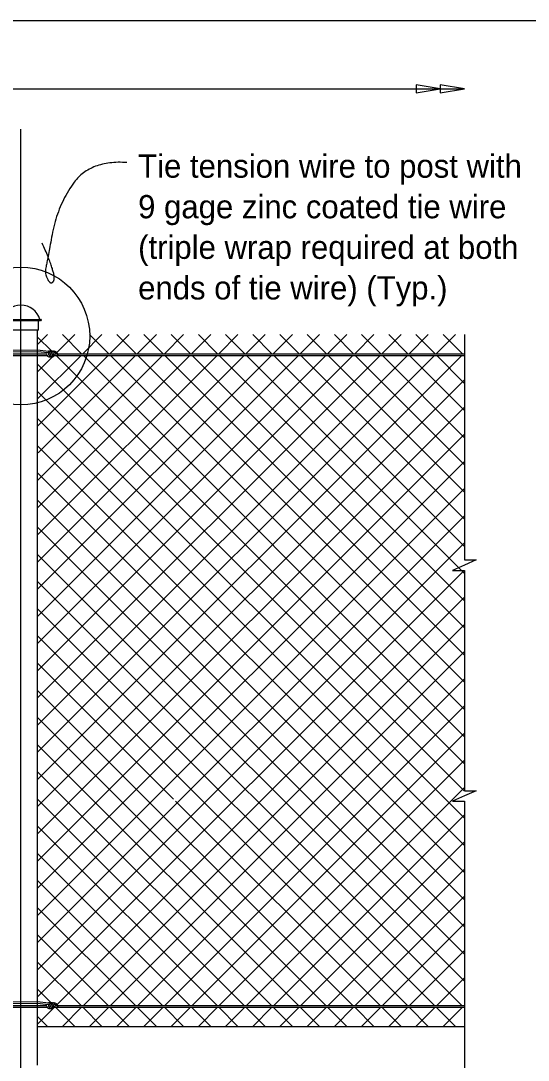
# Model space of a CAD drawing. Extents: x 0 to 72.1, y -15.2 to 30.1.
# Drawn here: x 24.63 to 29.03, y 18.99 to 28 of the extents above; entities that cross this region are included whole.
import ezdxf

# ---------------------------------------------------------------- set-up
doc = ezdxf.new("R2010")
doc.units = 0
for name, color, linetype in [('ActivePts-ConstElements', 7, 'Continuous'), ('AdhocPoint_dp', 7, 'Continuous'), ('Border', 7, 'Continuous'), ('Patterning', 7, 'Continuous'), ('PlotBorder_dp', 7, 'Continuous'), ('SheetBorder_dp', 7, 'Continuous'), ('TextMisc', 7, 'Continuous')]:
    doc.layers.add(name, color=color, linetype=linetype)

msp = doc.modelspace()

# ---------------------------------------------------------------- linework, layer by layer
at = {"layer": 'ActivePts-ConstElements'}
msp.add_lwpolyline([(0.016, 2.0538), (41.0666, 2.0538), (41.0666, 27.9999), (0.016, 27.9999)], close=True, dxfattribs=at)
at = {"layer": 'AdhocPoint_dp'}
for q in [(28.4755, 19.2783), (26.018, 19.2783)]:
    msp.add_line((24.7769, 19.2783), q, dxfattribs=at)
at = {"layer": 'Border'}
for p, q in [((24.4852, 25.1116), (24.7769, 25.1116)), ((24.4852, 25.0969), (24.7769, 25.0969)), ((24.4852, 19.4597), (24.7769, 19.4597)), ((24.4852, 19.445), (24.7769, 19.445))]:
    msp.add_line(p, q, dxfattribs=at)
at = {"layer": 'Patterning'}
for p, q in [((24.7769, 25.1917), (24.8635, 25.2783)), ((24.7769, 25.2575), (24.8992, 25.1352)), ((24.9441, 25.1232), (25.0992, 25.2783)), ((24.9918, 25.2783), (25.1584, 25.1116)), ((25.1682, 25.1116), (25.3349, 25.2783)), ((25.2275, 25.2783), (25.3941, 25.1116)), ((25.4039, 25.1116), (25.5706, 25.2783)), ((25.4632, 25.2783), (25.6298, 25.1116)), ((25.6396, 25.1116), (25.8063, 25.2783)), ((25.6989, 25.2783), (25.8655, 25.1116)), ((25.8753, 25.1116), (26.042, 25.2783)), ((25.9346, 25.2783), (26.1012, 25.1116)), ((26.111, 25.1116), (26.2777, 25.2783)), ((26.1703, 25.2783), (26.3369, 25.1116)), ((26.3467, 25.1116), (26.5134, 25.2783)), ((26.406, 25.2783), (26.5726, 25.1116)), ((26.5824, 25.1116), (26.7491, 25.2783)), ((26.6417, 25.2783), (26.8083, 25.1116)), ((26.8181, 25.1116), (26.9848, 25.2783)), ((26.8774, 25.2783), (27.044, 25.1116)), ((27.0538, 25.1116), (27.2205, 25.2783)), ((27.1131, 25.2783), (27.2797, 25.1116)), ((27.2896, 25.1116), (27.4562, 25.2783)), ((27.3488, 25.2783), (27.5154, 25.1116)), ((27.5253, 25.1116), (27.6919, 25.2783)), ((27.5845, 25.2783), (27.7511, 25.1116)), ((27.761, 25.1116), (27.9276, 25.2783)), ((27.8202, 25.2783), (27.9868, 25.1116)), ((27.9967, 25.1116), (28.1633, 25.2783)), ((28.0559, 25.2783), (28.2225, 25.1116)), ((28.2324, 25.1116), (28.399, 25.2783)), ((28.2916, 25.2783), (28.4582, 25.1116)), ((24.7769, 22.1276), (27.7462, 25.0969)), ((24.7769, 22.599), (27.2748, 25.0969)), ((24.7769, 23.0704), (26.8034, 25.0969)), ((24.7769, 23.5418), (26.332, 25.0969)), ((24.7769, 21.6562), (28.2176, 25.0969)), ((24.7769, 23.7775), (26.0963, 25.0969)), ((24.7769, 23.3061), (26.5677, 25.0969)), ((24.7769, 22.8347), (27.0391, 25.0969)), ((24.7769, 22.3633), (27.5105, 25.0969)), ((24.7769, 21.8919), (27.9819, 25.0969)), ((24.7769, 21.4205), (28.4533, 25.0969)), ((24.7769, 24.0132), (25.8606, 25.0969)), ((24.7769, 24.4846), (25.3892, 25.0969)), ((24.7769, 24.7203), (25.1535, 25.0969)), ((24.7769, 24.956), (24.9064, 25.0855)), ((24.7813, 24.2534), (25.6249, 25.0969)), ((24.9325, 25.1116), (24.937, 25.1161)), ((24.9375, 25.0969), (28.4755, 21.5588)), ((25.1732, 25.0969), (28.4755, 21.7945)), ((25.4089, 25.0969), (28.4755, 22.0302)), ((25.6446, 25.0969), (28.4755, 22.2659)), ((25.8803, 25.0969), (28.4755, 22.5016)), ((26.116, 25.0969), (28.4755, 22.7373)), ((26.3517, 25.0969), (28.4755, 22.973)), ((26.5874, 25.0969), (28.4755, 23.2087)), ((26.8231, 25.0969), (28.4755, 23.4444)), ((27.0588, 25.0969), (28.4755, 23.6801)), ((27.2945, 25.0969), (28.4755, 23.9158)), ((27.5302, 25.0969), (28.4755, 24.1515)), ((27.7659, 25.0969), (28.4755, 24.3872)), ((28.0016, 25.0969), (28.4755, 24.6229)), ((28.2373, 25.0969), (28.4755, 24.8586)), ((24.7769, 25.0218), (28.4755, 21.3231)), ((24.7769, 21.1848), (28.4755, 24.8834)), ((24.7769, 24.7861), (28.4755, 21.0874)), ((24.7769, 20.9491), (28.4755, 24.6477)), ((24.7769, 24.5503), (28.4755, 20.8517)), ((24.7769, 20.7134), (28.4755, 24.412)), ((24.7769, 24.3146), (28.4755, 20.616)), ((24.7769, 20.4777), (28.4755, 24.1763)), ((24.7769, 24.0789), (28.4755, 20.3803)), ((24.7769, 20.242), (28.4755, 23.9406)), ((24.7769, 23.8432), (28.4755, 20.1446)), ((24.7769, 20.0063), (28.4755, 23.7049)), ((24.7769, 23.6075), (28.4755, 19.9089)), ((24.7769, 19.7706), (28.4755, 23.4692)), ((24.7769, 23.3718), (28.4755, 19.6732)), ((24.7769, 19.5349), (28.4755, 23.2335)), ((24.7769, 23.1361), (28.4533, 19.4597)), ((24.9463, 19.4686), (28.4755, 22.9978)), ((24.7769, 22.9004), (28.2176, 19.4597)), ((25.1732, 19.4597), (28.4755, 22.7621)), ((24.7769, 22.6647), (27.9819, 19.4597)), ((25.4089, 19.4597), (28.4755, 22.5264)), ((24.7769, 22.429), (25.9555, 21.2505)), ((25.6446, 19.4597), (28.4755, 22.2907)), ((24.7769, 22.1933), (27.5105, 19.4597)), ((25.8803, 19.4597), (28.4755, 22.055)), ((24.7769, 21.9576), (27.2748, 19.4597)), ((26.116, 19.4597), (28.4755, 21.8193)), ((24.7769, 21.7219), (27.0391, 19.4597)), ((26.3517, 19.4597), (28.4755, 21.5836)), ((24.7769, 21.4862), (26.8034, 19.4597)), ((26.5874, 19.4597), (28.4755, 21.3479)), ((24.7769, 21.2505), (26.5677, 19.4597)), ((25.9733, 21.2327), (27.7462, 19.4597)), ((26.8231, 19.4597), (28.4755, 21.1122)), ((24.7769, 21.0148), (26.332, 19.4597)), ((27.0588, 19.4597), (28.4755, 20.8765)), ((24.7769, 20.7791), (26.0963, 19.4597)), ((27.2945, 19.4597), (28.4755, 20.6408)), ((24.7769, 20.5434), (25.8606, 19.4597)), ((27.5302, 19.4597), (28.4755, 20.4051)), ((24.7769, 20.3077), (25.6249, 19.4597)), ((27.7659, 19.4597), (28.4755, 20.1694)), ((24.7769, 20.072), (25.3892, 19.4597)), ((28.0016, 19.4597), (28.4755, 19.9337)), ((24.7769, 19.8363), (25.1535, 19.4597)), ((28.2373, 19.4597), (28.4755, 19.698)), ((24.7769, 19.6006), (24.8943, 19.4832)), ((24.7769, 19.2992), (24.9152, 19.4375)), ((24.9325, 19.445), (25.0992, 19.2783)), ((24.9918, 19.2783), (25.1584, 19.445)), ((25.1682, 19.445), (25.3349, 19.2783)), ((25.2275, 19.2783), (25.3941, 19.445)), ((25.4039, 19.445), (25.5706, 19.2783)), ((25.4632, 19.2783), (25.6298, 19.445)), ((25.6396, 19.445), (25.8063, 19.2783)), ((25.6989, 19.2783), (25.8655, 19.445)), ((25.8753, 19.445), (26.042, 19.2783)), ((25.9346, 19.2783), (26.1012, 19.445)), ((26.111, 19.445), (26.2777, 19.2783)), ((26.1703, 19.2783), (26.3369, 19.445)), ((26.3467, 19.445), (26.5134, 19.2783)), ((26.406, 19.2783), (26.5726, 19.445)), ((26.5824, 19.445), (26.7491, 19.2783)), ((26.6417, 19.2783), (26.8083, 19.445)), ((26.8181, 19.445), (26.9848, 19.2783)), ((26.8774, 19.2783), (27.044, 19.445)), ((27.0538, 19.445), (27.2205, 19.2783)), ((27.1131, 19.2783), (27.2797, 19.445)), ((27.2896, 19.445), (27.4562, 19.2783)), ((27.3488, 19.2783), (27.5154, 19.445)), ((27.5253, 19.445), (27.6919, 19.2783)), ((27.5845, 19.2783), (27.7511, 19.445)), ((27.761, 19.445), (27.9276, 19.2783)), ((27.8202, 19.2783), (27.9868, 19.445)), ((27.9967, 19.445), (28.1633, 19.2783)), ((28.0559, 19.2783), (28.2225, 19.445)), ((28.2324, 19.445), (28.399, 19.2783)), ((28.2916, 19.2783), (28.4582, 19.445)), ((24.7802, 19.3616), (24.8635, 19.2783))]:
    msp.add_line(p, q, dxfattribs=at)
at = {"layer": 'PlotBorder_dp'}
for points in [[(13.631, 27.4094), (15.0947, 27.4094), (15.0947, 27.5128), (15.1397, 27.4094), (15.1847, 27.3061), (15.1847, 27.4094), (28.4756, 27.4094)], [(28.4756, 25.2804), (28.4756, 23.3241), (28.5789, 23.3241), (28.4756, 23.2791), (28.3722, 23.2341), (28.4756, 23.2341), (28.4756, 22.3405)], [(28.4756, 22.3405), (28.4756, 21.3227), (28.5789, 21.3227), (28.4756, 21.2777), (28.3722, 21.2327), (28.4756, 21.2327), (28.4756, 19.0284)], [(28.4756, 19.2784), (28.4756, 17.4276), (28.5789, 17.4276), (28.4756, 17.3826), (28.3722, 17.3376), (28.4756, 17.3376), (28.4756, 15.5326)]]:
    msp.add_lwpolyline(points, dxfattribs=at)
for points in [[(28.2673, 27.4094), (28.0591, 27.4447), (28.0591, 27.3741)], [(28.4756, 27.4094), (28.2673, 27.4447), (28.2673, 27.3741)]]:
    msp.add_lwpolyline(points, close=True, dxfattribs=at)
msp.add_circle((24.631, 25.2659), 0.5976, dxfattribs=at)
msp.add_open_spline([(25.5508, 26.7708), (25.232, 26.7907), (24.9506, 26.4018), (24.8579, 25.9058), (24.8362, 25.8036), (24.8959, 25.7039), (24.9407, 25.7936), (24.8162, 26.0728)], degree=2, dxfattribs=at)
at = {"layer": 'SheetBorder_dp'}
msp.add_line((24.6311, 13.3896), (24.6311, 27.059), dxfattribs=at)
at = {"layer": 'TextMisc'}
for p, q in [((24.4587, 25.4103), (24.8033, 25.4103)), ((24.8033, 25.398), (24.4587, 25.398)), ((24.7851, 25.3183), (24.7851, 25.398)), ((24.7851, 25.3183), (24.477, 25.3183)), ((24.7769, 18.9432), (24.7769, 25.3183)), ((24.4852, 25.1443), (24.7764, 25.1459)), ((24.4852, 25.1297), (24.7764, 25.1314)), ((24.7764, 25.1459), (24.8707, 25.1348)), ((24.7764, 25.1314), (24.8685, 25.122)), ((24.7769, 25.1116), (24.8573, 25.1116)), ((24.7769, 25.0969), (24.86, 25.0969)), ((24.9227, 25.0969), (28.4755, 25.0969)), ((24.9276, 25.1116), (24.9429, 25.1116)), ((24.9514, 25.1116), (28.4755, 25.1116)), ((24.4852, 19.4923), (24.7764, 19.494)), ((24.4852, 19.4778), (24.7764, 19.4795)), ((24.7764, 19.494), (24.8707, 19.4829)), ((24.7764, 19.4795), (24.8685, 19.4701)), ((24.7769, 19.4597), (24.8573, 19.4597)), ((24.7769, 19.445), (24.86, 19.445)), ((24.9219, 19.445), (28.4755, 19.445)), ((24.9276, 19.4597), (24.9429, 19.4597)), ((24.9514, 19.4597), (28.4755, 19.4597))]:
    msp.add_line(p, q, dxfattribs=at)
msp.add_arc((24.8032, 25.404), 0.00613, 271.1647, 88.8353, dxfattribs=at)
for centre, major_axis, ratio, start_param, end_param in [((24.6317, 25.3692), (0.1711, 0), 0.957868, 0.252602, 2.888574), ((24.8821, 25.1081), (-0.0251, 0), 0.957868, 0.055352, 0.751829), ((24.8821, 25.1081), (-0.0251, 0), 0.957868, 5.673972, 5.875498), ((24.8892, 25.1202), (-0.0391, 0), 0.957868, 0.863445, 1.200597), ((24.8717, 25.11), (0.0303, -0.0108), 0.724765, 6.241815, 8.212701), ((24.8666, 25.0971), (0.0259, 0), 0.957868, 0.655696, 1.505671), ((24.8823, 25.1094), (-0.0119, 0), 0.957868, 5.149694, 6.840495), ((24.8823, 25.1094), (-0.0119, 0), 0.957868, 0.560069, 0.643501), ((24.8807, 25.1036), (0.00795, 0), 0.957868, 3.252108, 6.425997), ((24.8818, 25.1014), (-0.0206, -0.0021), 0.798607, 1.063032, 2.950031), ((24.8851, 25.1082), (-0.0295, 0), 0.957868, 2.243629, 5.062245), ((24.875, 25.106), (0.0139, 0), 0.957868, 5.660958, 7.342751), ((24.8953, 25.1014), (-0.0206, -0.0021), 0.798607, 1.063032, 1.956656), ((24.9039, 25.1136), (-0.023, 0), 0.957868, 3.312645, 4.992926), ((24.9014, 25.1071), (-0.0231, 0), 0.957868, 1.403365, 2.503632), ((24.9164, 25.0992), (-0.0373, 0), 0.957868, 3.175144, 4.79635), ((24.9028, 25.1111), (0.0249, 0), 0.957868, 5.476514, 6.557353), ((24.8953, 25.0595), (0.0724, 0), 0.957868, 0.631079, 1.121037), ((24.8717, 19.4581), (0.0303, -0.0108), 0.724765, 6.241815, 8.212701), ((24.8851, 19.4563), (-0.0295, 0), 0.957868, 2.243629, 5.062245), ((24.9039, 19.4617), (-0.023, 0), 0.957868, 3.312645, 4.992926), ((24.9164, 19.4472), (-0.0373, 0), 0.957868, 3.175144, 4.79635), ((24.8821, 19.4562), (-0.0251, 0), 0.957868, 0.055352, 0.751829), ((24.8821, 19.4562), (-0.0251, 0), 0.957868, 5.673972, 5.875498), ((24.8892, 19.4683), (-0.0391, 0), 0.957868, 0.863445, 1.200597), ((24.8666, 19.4452), (0.0259, 0), 0.957868, 0.655696, 1.505671), ((24.8823, 19.4575), (-0.0119, 0), 0.957868, 5.149694, 6.840495), ((24.8823, 19.4575), (-0.0119, 0), 0.957868, 0.560069, 0.643501), ((24.8807, 19.4517), (0.00795, 0), 0.957868, 3.252108, 6.425997), ((24.8818, 19.4495), (-0.0206, -0.0021), 0.798607, 1.063032, 2.950031), ((24.875, 19.454), (0.0139, 0), 0.957868, 5.660958, 7.342751), ((24.8953, 19.4495), (-0.0206, -0.0021), 0.798607, 1.063032, 1.956656), ((24.9014, 19.4552), (-0.0231, 0), 0.957868, 1.403365, 2.503632), ((24.9028, 19.4592), (0.0249, 0), 0.957868, 5.476514, 6.557353), ((24.8953, 19.4075), (0.0724, 0), 0.957868, 0.631079, 1.121037)]:
    msp.add_ellipse(centre, major_axis=major_axis, ratio=ratio, start_param=start_param, end_param=end_param, dxfattribs=at)

# ---------------------------------------------------------------- texts
at = {"layer": 'PlotBorder_dp'}
for s, p in [('Tie tension wire to post with ', (25.648, 26.6391)), ('9 gage zinc coated tie wire ', (25.648, 26.2871)), ('(triple wrap required at both ', (25.648, 25.9351)), ('ends of tie wire) (Typ.)', (25.648, 25.5831))]:
    msp.add_text(s, height=0.2016, dxfattribs=at).set_placement(p)

doc.saveas('drawing.dxf')
